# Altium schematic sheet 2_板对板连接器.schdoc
size 307 x 218 mm; Symbol: Drawing-Symbol_A4; Device: Drawing-Symbol_A4; Company: 嘉立创EDA; Version: V1.0; Page Size: A4; @Project Name: New Project_2025-01-23_00-40-50; @Page Count: 4; @Update Date: 2025-08-15; @Create Date: 2025-07-30; @Schematic Name: Schematic3_7; @Page No: 2; @Page Name: 板对板连接器; @Create Time: 15:34:35; @Update Time: 16:25:58; Width: 1170; Height: 825; Region Start: 1; X Region Count: 6; Y Region Count: 4; Blade Width: 10; Title Block Position: 3; @Board Name: cm4
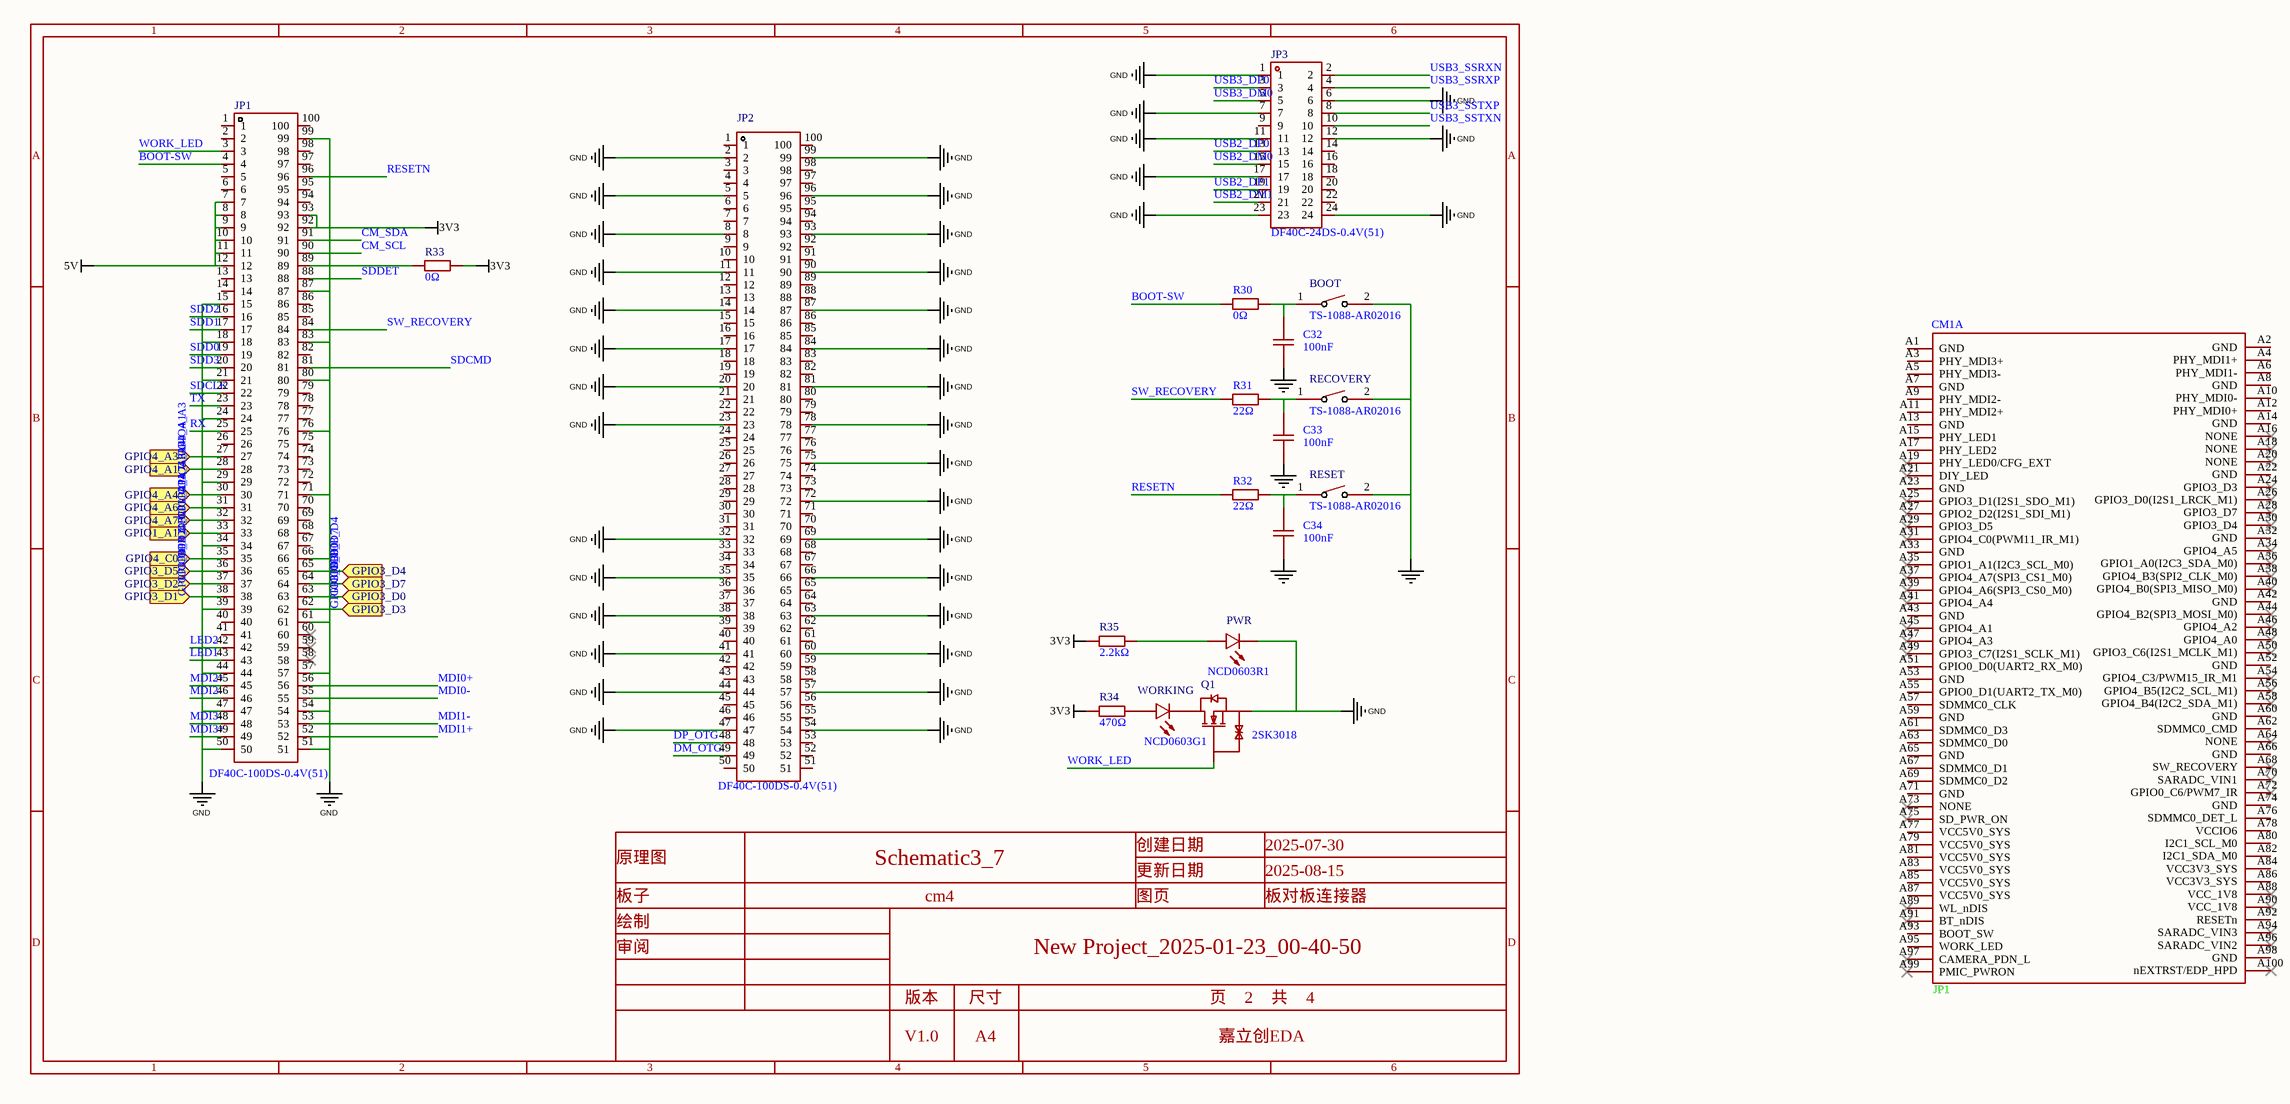
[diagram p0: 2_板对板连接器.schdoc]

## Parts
BOOT  TS-1088-AR02016  [SW-SMD_L3.9-W3.0-P4.45]
C32  100nF  [C0603]
C33  100nF  [C0603]
C34  100nF  [C0603]
CM1  (no value)  [Orange Pi CM4]  (part A of 4)
JP1  DF40C-100DS-0.4V(51)  [CONN-SMD_DF40C-100DS-0.4V-51]
JP2  DF40C-100DS-0.4V(51)  [CONN-SMD_DF40C-100DS-0.4V-51]
JP3  DF40C-24DS-0.4V(51)  [CONN-SMD_DF40C-24DS-0.4V51]
PWR  NCD0603R1  [LED0603-RD_RED]
Q1  2SK3018  [SOT-23-3_L2.9-W1.4-P1.90-LS2.6-BR]
R30  0Ω  [R0603]
R31  22Ω  [R0603]
R32  22Ω  [R0603]
R33  0Ω  [R0603]
R34  470Ω  [R0603]
R35  2.2kΩ  [R0603]
RECOVERY  TS-1088-AR02016  [SW-SMD_L3.9-W3.0-P4.45]
RESET  TS-1088-AR02016  [SW-SMD_L3.9-W3.0-P4.45]
WORKING  NCD0603G1  [LED0603-RD_1]

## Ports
GPIO1_A1 (in), GPIO3_D0 (in), GPIO3_D1 (in), GPIO3_D2 (in), GPIO3_D3 (in), GPIO3_D4 (in), GPIO3_D5 (in), GPIO3_D7 (in), GPIO4_A1 (in), GPIO4_A3 (in), GPIO4_A4 (in), GPIO4_A6 (in), GPIO4_A7 (in), GPIO4_C0 (in)

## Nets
3V3: JP1.92 JP1.93 R33.2 R34.2 R35.2
5V: JP1.7 JP1.8 JP1.9 JP1.10 JP1.11 JP1.12
GND: BOOT.2 C32.2 C33.2 C34.2 JP1.15 JP1.18 JP1.21 JP1.24 JP1.29 JP1.34 JP1.39 JP1.44 JP1.47 JP1.50 JP1.51 JP1.54 JP1.57 JP1.61 JP1.66 JP1.71 JP1.76 JP1.80 JP1.83 JP1.87 JP1.99 JP2.2 JP2.5 JP2.8 JP2.11 JP2.14 JP2.17 JP2.20 JP2.23 JP2.32 JP2.35 JP2.38 JP2.41 JP2.44 JP2.47 JP2.54 JP2.57 JP2.60 JP2.63 JP2.66 JP2.69 JP2.72 JP2.75 JP2.78 JP2.81 JP2.84 JP2.87 JP2.90 JP2.93 JP2.96 JP2.99 JP3.1 JP3.6 JP3.7 JP3.11 JP3.12 JP3.17 JP3.23 JP3.24 PWR.1(K) Q1.2(S) RECOVERY.2 RESET.2
BOOT-SW: JP1.4 R30.1
CM_SCL: JP1.90
CM_SDA: JP1.91
DM_OTG: JP2.49
DP_OTG: JP2.48
GPIO1_A1: JP1.33 ; port GPIO1_A1
GPIO3_D0: JP1.63 ; port GPIO3_D0
GPIO3_D1: JP1.38 ; port GPIO3_D1
GPIO3_D2: JP1.37 ; port GPIO3_D2
GPIO3_D3: JP1.62 ; port GPIO3_D3
GPIO3_D4: JP1.65 ; port GPIO3_D4
GPIO3_D5: JP1.36 ; port GPIO3_D5
GPIO3_D7: JP1.64 ; port GPIO3_D7
GPIO4_A1: JP1.28 ; port GPIO4_A1
GPIO4_A3: JP1.27 ; port GPIO4_A3
GPIO4_A4: JP1.30 ; port GPIO4_A4
GPIO4_A6: JP1.31 ; port GPIO4_A6
GPIO4_A7: JP1.32 ; port GPIO4_A7
GPIO4_C0: JP1.35 ; port GPIO4_C0
LED1: JP1.43
LED2: JP1.42
MDI0+: JP1.56
MDI0-: JP1.55
MDI1+: JP1.52
MDI1-: JP1.53
MDI2+: JP1.45
MDI2-: JP1.46
MDI3+: JP1.49
MDI3-: JP1.48
RESETN: JP1.96 R32.1
RX: JP1.25
SDCLK: JP1.22
SDCMD: JP1.81
SDD0: JP1.19
SDD1: JP1.17
SDD2: JP1.16
SDD3: JP1.20
SDDET: JP1.88
SW_RECOVERY: JP1.84 R31.1
TX: JP1.23
USB2_DM0: JP3.15
USB2_DM1: JP3.21
USB2_DP0: JP3.13
USB2_DP1: JP3.19
USB3_DM0: JP3.5
USB3_DP0: JP3.3
USB3_SSRXN: JP3.2
USB3_SSRXP: JP3.4
USB3_SSTXN: JP3.10
USB3_SSTXP: JP3.8
WORK_LED: JP1.3 Q1.1(G)
NetBOOT_1: BOOT.1 C32.1 R30.2
NetC33_1: C33.1 R31.2 RECOVERY.1
NetC34_1: C34.1 R32.2 RESET.1
NetJP1_89: JP1.89 R33.1
NetPWR_2: PWR.2(A) R35.1
NetQ1_3: Q1.3(D) WORKING.1(K)
NetR34_1: R34.1 WORKING.2(A)

Not connected (* = marked no-connect by the designer): CM1 A1(GND) A2(GND) A3(PHY_MDI3+) A4(PHY_MDI1+) A5(PHY_MDI3-) A6(PHY_MDI1-) A7(GND) A8(GND) A9(PHY_MDI2-) A10(PHY_MDI0-) A11(PHY_MDI2+) A12(PHY_MDI0+) A13(GND) A14(GND) A15(PHY_LED1) A16(NONE)* A17(PHY_LED2) A18(NONE)* A19(PHY_LED0/CFG_EXT)* A20(NONE)* A21(DIY_LED)* A22(GND) A23(GND) A24(GPIO3_D3)* A25(GPIO3_D1(I2S1_SDO_M1))* A26(GPIO3_D0(I2S1_LRCK_M1))* A27(GPIO2_D2(I2S1_SDI_M1))* A28(GPIO3_D7)* A29(GPIO3_D5)* A30(GPIO3_D4)* A31(GPIO4_C0(PWM11_IR_M1))* A32(GND) A33(GND) A34(GPIO4_A5)* A35(GPIO1_A1(I2C3_SCL_M0))* A36(GPIO1_A0(I2C3_SDA_M0))* A37(GPIO4_A7(SPI3_CS1_M0))* A38(GPIO4_B3(SPI2_CLK_M0))* A39(GPIO4_A6(SPI3_CS0_M0))* A40(GPIO4_B0(SPI3_MISO_M0))* A41(GPIO4_A4)* A42(GND) A43(GND) A44(GPIO4_B2(SPI3_MOSI_M0))* A45(GPIO4_A1)* A46(GPIO4_A2)* A47(GPIO4_A3)* A48(GPIO4_A0)* A49(GPIO3_C7(I2S1_SCLK_M1))* A50(GPIO3_C6(I2S1_MCLK_M1))* A51(GPIO0_D0(UART2_RX_M0)) A52(GND) A53(GND) A54(GPIO4_C3/PWM15_IR_M1)* A55(GPIO0_D1(UART2_TX_M0)) A56(GPIO4_B5(I2C2_SCL_M1))* A57(SDMMC0_CLK) A58(GPIO4_B4(I2C2_SDA_M1))* A59(GND) A60(GND) A61(SDMMC0_D3) A62(SDMMC0_CMD) A63(SDMMC0_D0) A64(NONE)* A65(GND) A66(GND) A67(SDMMC0_D1) A68(SW_RECOVERY)* A69(SDMMC0_D2) A70(SARADC_VIN1)* A71(GND) A72(GPIO0_C6/PWM7_IR)* A73(NONE)* A74(GND) A75(SD_PWR_ON)* A76(SDMMC0_DET_L) A77(VCC5V0_SYS) A78(VCCIO6) A79(VCC5V0_SYS) A80(I2C1_SCL_M0) A81(VCC5V0_SYS) A82(I2C1_SDA_M0) A83(VCC5V0_SYS) A84(VCC3V3_SYS) A85(VCC5V0_SYS) A86(VCC3V3_SYS) A87(VCC5V0_SYS) A88(VCC_1V8)* A89(WL_nDIS)* A90(VCC_1V8)* A91(BT_nDIS)* A92(RESETn) A93(BOOT_SW) A94(SARADC_VIN3)* A95(WORK_LED) A96(SARADC_VIN2)* A97(CAMERA_PDN_L)* A98(GND) A99(PMIC_PWRON)* A100(nEXTRST/EDP_HPD)*; JP1 1 2 5 6 13 14 26 40 41 58* 59* 60* 67 68 69 70 72 73 74 75 77 78 79 82 85 86 94 95 97 98 100; JP2 1 3 4 6 7 9 10 12 13 15 16 18 19 21 22 24 25 26 27 28 29 30 31 33 34 36 37 39 40 42 43 45 46 50 51 52 53 55 56 58 59 61 62 64 65 67 68 70 71 73 74 76 77 79 80 82 83 85 86 88 89 91 92 94 95 97 98 100; JP3 9 14 16 18 20 22

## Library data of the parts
BOOT RECOVERY RESET = TS-1088-AR02016: Manufacturer: XUNPU(讯普); Add into BOM: yes; Circuit: 单刀单掷; Actuator Style: 圆形按钮; Operating Force: 160gf; Switch Length: 4mm; Switch Width: 3mm; Switch Height: 2mm; Strike Gundam: 不带; Contact Current: 50mA; Voltage Rating (DC): 12V; Insulation Resistance: 100MΩ; Actuator/Cap Color: 黑色; Pin Style: SMD接片; Mechanical Life: 10万次
C32-C34 = CC0603KRX7R9BB104: Manufacturer: YAGEO(国巨); Symbol: Capacitance; Add into BOM: yes; Tolerance: ±10%; Voltage Rated: 50V; Temperature Coefficient: X7R
CM1 = Orange Pi CM4: Add into BOM: no; Convert to PCB: yes
JP1 JP2 = DF40C-100DS-0.4V(51): Manufacturer: HRS(广濑); Add into BOM: yes; Pitch: 0.4mm; Current Rating: 300mA
JP3 = DF40C-24DS-0.4V(51): Manufacturer: HRS(广濑); Add into BOM: yes; Pitch: 0.4mm; Gender: 母; Current Rating (Max): 300mA
PWR = NCD0603R1_C84263: Manufacturer: 国星光电; Symbol: FC-DA1608HRK-620D; Add into BOM: yes; Emitted Color: 红色; Forward Voltage (VF): 1.6V~2.6V; Power Dissipation: 65mW; Forward Current: 20mA; Dominant Wavelength: 615nm~630nm; Diode Configuration: 独立二极管; Lens Color: 无色透明透镜; Luminous Intensity: 80mcd~220mcd; Viewing Angle: 130°
Q1 = 2SK3018: Manufacturer: TWGMC(台湾迪嘉); Symbol: 2SK3018_C727148; Add into BOM: yes
R30 = 0603WAF0000T5E: Manufacturer: UNI-ROYAL(厚声); Symbol: 电阻; Add into BOM: yes; Tolerance: ±1%; Power(Watts): 100mW; Overload Voltage (Max): 75V
R31 R32 = 0603WAF220JT5E: Manufacturer: UNI-ROYAL(厚声); Symbol: 电阻; Add into BOM: yes; Tolerance: ±1%; Power(Watts): 100mW; Overload Voltage (Max): 75V; Temperature Coefficient: ±100ppm/℃
R33 = 0603WAF0000T5E: Manufacturer: UNI-ROYAL(厚声); Add into BOM: yes; Tolerance: ±1%; Power(Watts): 100mW; Overload Voltage (Max): 75V
R34 = 0603WAF4700T5E: Manufacturer: UNI-ROYAL(厚声); Add into BOM: yes; Tolerance: ±1%; Power(Watts): 100mW; Overload Voltage (Max): 75V; Temperature Coefficient: ±100ppm/℃
R35 = 0603WAF2201T5E: Manufacturer: UNI-ROYAL(厚声); Add into BOM: yes; Tolerance: ±1%; Power(Watts): 100mW; Overload Voltage (Max): 75V; Temperature Coefficient: ±100ppm/℃
WORKING = NCD0603G1: Manufacturer: 国星光电; Symbol: FC-DA1608HRK-620D; Add into BOM: yes; Illumination Color: 翠绿色; Voltage - Forward(Vf): 2.6V~3.6V; Power(Watts): 72mW; Forward Current: 20mA; Wavelength - Dominant: 515nm~530nm; Luminous Intensity: 330mcd~900mcd; Viewing Angle: 130°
